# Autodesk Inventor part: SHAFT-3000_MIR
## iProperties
Created: 2007-08
Part Number: SHAFT-3000_MIR
Material: Stainless Steel
Document SubType Name: Modeling
Density: 8.08 g/cm^3
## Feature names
1. Derived Body1 [Tagging]
